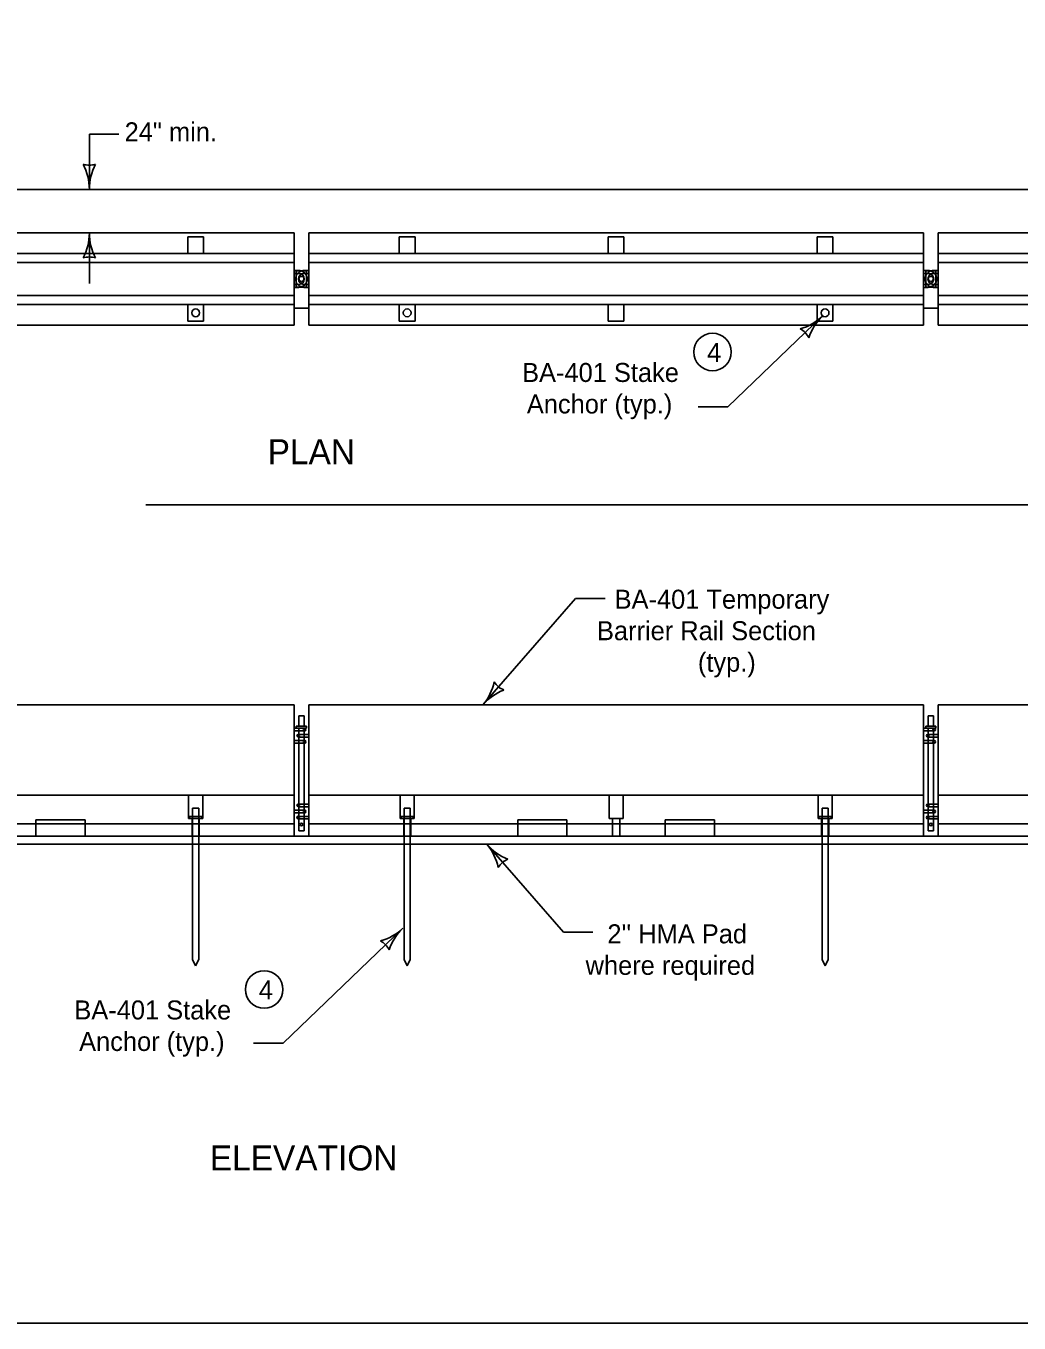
# Model space of a CAD drawing. Extents: x 10028 to 81668, y 3581 to 11018.
# Drawn here: x 22150 to 22944, y 7924 to 8962 of the extents above; entities that cross this region are included whole.
import ezdxf

# ---------------------------------------------------------------- set-up
doc = ezdxf.new("R2010")
doc.units = 0
for name, color, linetype in [('conPaving', 7, 'Continuous'), ('dsnCellsNorthArrow', 7, 'Continuous'), ('dsnTextTabulation', 7, 'Continuous'), ('Level 41', 7, 'Continuous'), ('Level 9', 7, 'Continuous'), ('SheetBorder', 7, 'Continuous')]:
    doc.layers.add(name, color=color, linetype=linetype)

msp = doc.modelspace()

# ---------------------------------------------------------------- linework, layer by layer
at = {"layer": 'conPaving'}
for p, q in [((22283.3, 8313.6), (22282.9, 8313.6)), ((22283.3, 8307.1), (22283.3, 8313.6)), ((22288.6, 8313.6), (22288.2, 8313.6)), ((22288.2, 8313.6), (22288.2, 8307.1)), ((22364.1, 8313.6), (22288.6, 8313.6)), ((22452.5, 8313.6), (22452.1, 8313.6)), ((22452.5, 8307.1), (22452.5, 8313.6)), ((22457.4, 8313.6), (22457.4, 8307.1)), ((22700.7, 8313.6), (22661.3, 8313.6)), ((22786.7, 8307.1), (22786.7, 8313.6)), ((22791.6, 8313.6), (22791.6, 8307.1)), ((22121.1, 8307.1), (22283.3, 8307.1)), ((22288.2, 8307.1), (22452.5, 8307.1)), ((22457.4, 8307.1), (22518.6, 8307.1)), ((22518.6, 8307.1), (22786.7, 8307.1)), ((22791.6, 8307.1), (22955.9, 8307.1))]:
    msp.add_line(p, q, dxfattribs=at)
for points in [[(22282.9, 8313.6), (22197.3, 8313.6), (22157.9, 8313.6), (22121.5, 8313.6), (22121.1, 8313.6)], [(22452.1, 8313.6), (22376.5, 8313.6), (22364.1, 8313.6)], [(22619.2, 8313.6), (22582.7, 8313.6), (22543.4, 8313.6), (22457.7, 8313.6), (22457.4, 8313.6)], [(22661.3, 8313.6), (22624.9, 8313.6), (22619.2, 8313.6)], [(22786.7, 8313.6), (22786.3, 8313.6), (22700.7, 8313.6)], [(22879.9, 8313.6), (22867.5, 8313.6), (22792, 8313.6), (22791.6, 8313.6)], [(22955.9, 8313.6), (22955.5, 8313.6), (22879.9, 8313.6)], [(22518.6, 8307.1), (22518.6, 8307.1)]]:
    msp.add_lwpolyline(points, dxfattribs=at)
msp.add_arc((22550.9, 8334.6), 42.5, 220.4336, 220.435, dxfattribs=at)
at = {"layer": 'dsnTextTabulation'}
for p, q in [((22200.7, 8831), (22200.7, 8875.1)), ((22200.7, 8875.1), (22224.3, 8875.1)), ((22364.4, 8796.1), (21872.9, 8796.1)), ((22200.7, 8755.8), (22200.7, 8796.1)), ((22364.4, 8722.4), (22364.4, 8796.1)), ((22867.8, 8796.1), (22376.3, 8796.1)), ((22376.3, 8722.4), (22376.3, 8796.1)), ((22867.8, 8722.4), (22867.8, 8796.1)), ((23371.2, 8796.1), (22879.7, 8796.1)), ((22879.7, 8722.4), (22879.7, 8796.1)), ((22364.4, 8779.8), (21872.9, 8779.8)), ((22867.8, 8779.8), (22376.3, 8779.8)), ((23371.2, 8779.8), (22879.7, 8779.8)), ((22364.4, 8772.4), (21872.9, 8772.4)), ((22867.8, 8772.4), (22376.3, 8772.4)), ((23371.2, 8772.4), (22879.7, 8772.4)), ((22364.4, 8746.2), (21872.9, 8746.2)), ((22364.4, 8738.8), (21872.9, 8738.8)), ((22867.8, 8746.2), (22376.3, 8746.2)), ((22867.8, 8738.8), (22376.3, 8738.8)), ((23371.2, 8746.2), (22879.7, 8746.2)), ((23371.2, 8738.8), (22879.7, 8738.8)), ((22711.4, 8657), (22787.1, 8729.7)), ((22364.4, 8722.4), (21872.9, 8722.4)), ((22867.8, 8722.4), (22376.3, 8722.4)), ((23371.2, 8722.4), (22879.7, 8722.4)), ((22687.7, 8657), (22711.4, 8657)), ((22245.9, 8578.7), (23377.1, 8578.7)), ((22515.3, 8418.5), (22589.6, 8503.7)), ((22589.6, 8503.7), (22613.2, 8503.7)), ((21872.9, 8418.5), (22364.4, 8418.5)), ((22364.4, 8313.9), (22364.4, 8418.5)), ((22376.3, 8313.9), (22376.3, 8418.5)), ((22376.3, 8418.5), (22867.8, 8418.5)), ((22867.8, 8313.9), (22867.8, 8418.5)), ((22879.7, 8313.9), (22879.7, 8418.5)), ((22879.7, 8418.5), (23371.2, 8418.5)), ((21872.9, 8346.4), (22364.4, 8346.4)), ((22376.3, 8346.4), (22867.8, 8346.4)), ((22879.7, 8346.4), (23371.2, 8346.4)), ((21872.9, 8323.4), (22364.4, 8323.4)), ((22157.9, 8326.7), (22197.3, 8326.7)), ((22157.9, 8313.6), (22157.9, 8323.4)), ((22197.3, 8313.6), (22197.3, 8323.4)), ((22376.3, 8323.4), (22867.8, 8323.4)), ((22543.4, 8326.7), (22582.7, 8326.7)), ((22543.4, 8313.6), (22543.4, 8323.4)), ((22582.7, 8313.6), (22582.7, 8323.4)), ((22661.3, 8326.7), (22700.7, 8326.7)), ((22661.3, 8313.6), (22661.3, 8323.4)), ((22700.7, 8313.6), (22700.7, 8323.4)), ((22879.7, 8323.4), (23371.2, 8323.4)), ((22079.3, 8313.6), (22157.9, 8313.6)), ((22197.3, 8313.6), (22364.1, 8313.6)), ((22376.5, 8313.6), (22543.4, 8313.6)), ((22582.7, 8313.6), (22661.3, 8313.6)), ((22700.7, 8313.6), (22867.5, 8313.6)), ((22879.9, 8313.6), (23046.8, 8313.6)), ((22518.6, 8307.1), (22579.8, 8236.8)), ((22355.6, 8148), (22451.5, 8239.9)), ((22579.8, 8236.8), (22603.4, 8236.8)), ((22332, 8148), (22355.6, 8148))]:
    msp.add_line(p, q, dxfattribs=at)
for centre in [(22699.1, 8700.9), (22340.5, 8190.9)]:
    msp.add_circle(centre, 15, dxfattribs=at)
for centre, radius, start, end in [((22200.7, 8866.7), 16.4, 252.2666, 287.7333), ((22158.2, 8831), 42.5, 360, 28.0725), ((22243.2, 8831), 42.5, 151.9275, 180), ((22158.2, 8796.1), 42.5, 331.9275, 360), ((22243.2, 8796.1), 42.5, 180, 208.0725), ((22200.7, 8760.5), 16.4, 72.2666, 107.7334), ((22757.7, 8760.3), 42.5, 285.7371, 313.8096), ((22816.5, 8699), 42.5, 133.8096, 161.8821), ((22761.4, 8705), 16.4, 26.0762, 61.5429), ((22483, 8446), 42.5, 319.5664, 347.6389), ((22538.5, 8445.6), 16.4, 211.833, 247.2997), ((22547.7, 8390.9), 42.5, 111.4939, 139.5664), ((22486.2, 8279.5), 42.5, 12.3611, 40.4336), ((22550.9, 8334.6), 42.5, 220.4336, 248.5061), ((22541.7, 8279.9), 16.4, 112.7003, 148.167), ((22422.1, 8270.6), 42.5, 285.7371, 313.8096), ((22480.9, 8209.3), 42.5, 133.8096, 161.8821), ((22425.8, 8215.3), 16.4, 26.0762, 61.5429)]:
    msp.add_arc(centre, radius, start, end, dxfattribs=at)
at = {"layer": 'Level 41'}
for p, q in [((22279.5, 8793), (22279.5, 8779.8)), ((22279.5, 8793), (22292, 8793)), ((22292, 8793), (22292, 8779.8)), ((22448.6, 8793), (22461.2, 8793)), ((22448.6, 8793), (22448.6, 8779.8)), ((22461.2, 8793), (22461.2, 8779.8)), ((22615.7, 8793), (22628.3, 8793)), ((22615.7, 8793), (22615.7, 8779.8)), ((22628.3, 8793), (22628.3, 8779.8)), ((22782.9, 8793), (22782.9, 8779.8)), ((22782.9, 8793), (22795.4, 8793)), ((22795.4, 8793), (22795.4, 8779.8)), ((22364.4, 8766), (22368.3, 8766)), ((22364.4, 8763.6), (22368.3, 8763.6)), ((22376.3, 8766), (22372.3, 8766)), ((22376.3, 8763.6), (22372.3, 8763.6)), ((22867.8, 8766), (22871.7, 8766)), ((22867.8, 8763.6), (22871.7, 8763.6)), ((22879.7, 8766), (22875.7, 8766)), ((22879.7, 8763.6), (22875.7, 8763.6)), ((22364.4, 8755), (22368.3, 8755)), ((22364.4, 8752.6), (22368.3, 8752.6)), ((22376.3, 8755), (22372.3, 8755)), ((22376.3, 8752.6), (22372.3, 8752.6)), ((22867.8, 8755), (22871.7, 8755)), ((22867.8, 8752.6), (22871.7, 8752.6)), ((22879.7, 8755), (22875.7, 8755)), ((22879.7, 8752.6), (22875.7, 8752.6)), ((22279.5, 8738.8), (22279.5, 8725.5)), ((22292, 8738.8), (22292, 8725.5)), ((22448.6, 8738.8), (22448.6, 8725.5)), ((22461.2, 8738.8), (22461.2, 8725.5)), ((22615.7, 8738.8), (22615.7, 8725.5)), ((22628.3, 8738.8), (22628.3, 8725.5)), ((22782.9, 8738.8), (22782.9, 8725.5)), ((22795.4, 8738.8), (22795.4, 8725.5)), ((22279.5, 8725.5), (22292, 8725.5)), ((22448.6, 8725.5), (22461.2, 8725.5)), ((22615.7, 8725.5), (22628.3, 8725.5)), ((22782.9, 8725.5), (22795.4, 8725.5)), ((22364.4, 8399.9), (22372.9, 8399.9)), ((22364.4, 8397.7), (22372.9, 8397.7)), ((22867.8, 8399.9), (22876.3, 8399.9)), ((22867.8, 8397.7), (22876.3, 8397.7)), ((22364.4, 8390), (22372.9, 8390)), ((22364.4, 8387.9), (22372.9, 8387.9)), ((22367.8, 8394.9), (22376.3, 8394.9)), ((22367.8, 8392.8), (22376.3, 8392.8)), ((22867.8, 8390), (22876.3, 8390)), ((22867.8, 8387.9), (22876.3, 8387.9)), ((22871.2, 8394.9), (22879.7, 8394.9)), ((22871.2, 8392.8), (22879.7, 8392.8)), ((22280.1, 8327.8), (22280.1, 8346.4)), ((22291.4, 8327.8), (22291.4, 8346.4)), ((22449.2, 8327.8), (22449.2, 8346.4)), ((22460.6, 8327.8), (22460.6, 8346.4)), ((22616.4, 8327.8), (22616.4, 8346.4)), ((22627.7, 8327.8), (22627.7, 8346.4)), ((22783.5, 8327.8), (22783.5, 8346.4)), ((22794.8, 8327.8), (22794.8, 8346.4)), ((22364.4, 8334.3), (22372.9, 8334.3)), ((22367.8, 8339.2), (22376.3, 8339.2)), ((22367.8, 8337.1), (22376.3, 8337.1)), ((22867.8, 8334.3), (22876.3, 8334.3)), ((22871.2, 8339.2), (22879.7, 8339.2)), ((22871.2, 8337.1), (22879.7, 8337.1)), ((22280.1, 8327.8), (22291.4, 8327.8)), ((22282.9, 8313.6), (22282.9, 8327.8)), ((22288.6, 8313.6), (22288.6, 8327.8)), ((22364.4, 8332.2), (22372.9, 8332.2)), ((22367.8, 8329.4), (22376.3, 8329.4)), ((22367.8, 8327.3), (22376.3, 8327.3)), ((22449.2, 8327.8), (22460.6, 8327.8)), ((22452.1, 8313.6), (22452.1, 8327.8)), ((22457.7, 8313.6), (22457.7, 8327.8)), ((22616.4, 8327.8), (22627.7, 8327.8)), ((22619.2, 8313.6), (22619.2, 8327.8)), ((22624.9, 8313.6), (22624.9, 8327.8)), ((22783.5, 8327.8), (22794.8, 8327.8)), ((22786.3, 8313.6), (22786.3, 8327.8)), ((22792, 8313.6), (22792, 8327.8)), ((22867.8, 8332.2), (22876.3, 8332.2)), ((22871.2, 8329.4), (22879.7, 8329.4)), ((22871.2, 8327.3), (22879.7, 8327.3))]:
    msp.add_line(p, q, dxfattribs=at)
for centre, radius in [((22285.7, 8732.2), 3.15), ((22454.9, 8732.2), 3.15), ((22789.1, 8732.2), 3.15), ((22372.9, 8398.8), 1.06), ((22876.3, 8398.8), 1.06), ((22367.8, 8393.9), 1.06), ((22372.9, 8389), 1.06), ((22871.2, 8393.9), 1.06), ((22876.3, 8389), 1.06), ((22367.8, 8338.2), 1.06), ((22372.9, 8333.3), 1.06), ((22871.2, 8338.2), 1.06), ((22876.3, 8333.3), 1.06), ((22367.8, 8328.4), 1.06), ((22871.2, 8328.4), 1.06)]:
    msp.add_circle(centre, radius, dxfattribs=at)
for centre, radius, start, end in [((22372.3, 8759.3), 6.68, 90, 270), ((22372.3, 8759.3), 4.33, 90, 270), ((22368.3, 8759.3), 6.68, 270, 90), ((22368.3, 8759.3), 4.33, 270, 90), ((22875.7, 8759.3), 6.68, 90, 270), ((22875.7, 8759.3), 4.33, 90, 270), ((22871.7, 8759.3), 6.68, 270, 90), ((22871.7, 8759.3), 4.33, 270, 90)]:
    msp.add_arc(centre, radius, start, end, dxfattribs=at)
at = {"layer": 'Level 9'}
for p, q in [((21357.6, 8831), (23377.1, 8831)), ((22376.3, 8796.1), (22867.8, 8796.1)), ((22879.7, 8796.1), (23371.2, 8796.1)), ((22364.4, 8766), (22368.3, 8766)), ((22366.2, 8765.8), (22374.4, 8765.8)), ((22366.2, 8752.7), (22366.2, 8765.8)), ((22369.8, 8765.8), (22370.9, 8765.8)), ((22372.3, 8766), (22376.3, 8766)), ((22374.4, 8765.8), (22374.4, 8752.7)), ((22867.8, 8766), (22871.7, 8766)), ((22869.6, 8765.8), (22877.8, 8765.8)), ((22869.6, 8752.7), (22869.6, 8765.8)), ((22873.2, 8765.8), (22874.3, 8765.8)), ((22875.7, 8766), (22879.7, 8766)), ((22877.8, 8765.8), (22877.8, 8752.7)), ((22368.3, 8752.6), (22364.4, 8752.6)), ((22374.4, 8752.7), (22366.2, 8752.7)), ((22371.1, 8752.7), (22369.5, 8752.7)), ((22376.3, 8752.6), (22372.3, 8752.6)), ((22871.7, 8752.6), (22867.8, 8752.6)), ((22877.8, 8752.7), (22869.6, 8752.7)), ((22874.5, 8752.7), (22872.9, 8752.7)), ((22879.7, 8752.6), (22875.7, 8752.6)), ((22364.4, 8736), (22376.3, 8736)), ((22364.4, 8736), (22376.3, 8736)), ((22867.8, 8736), (22879.7, 8736)), ((22867.8, 8736), (22879.7, 8736)), ((22368.3, 8409.7), (22372.4, 8409.7)), ((22368.3, 8401.5), (22368.3, 8409.7)), ((22372.4, 8409.7), (22372.4, 8401.5)), ((22871.7, 8409.7), (22875.8, 8409.7)), ((22871.7, 8401.5), (22871.7, 8409.7)), ((22875.8, 8409.7), (22875.8, 8401.5)), ((22366.2, 8401.5), (22374.4, 8401.5)), ((22366.2, 8399.9), (22366.2, 8401.5)), ((22374.4, 8399.9), (22366.2, 8399.9)), ((22368.3, 8317.9), (22368.3, 8399.9)), ((22372.4, 8399.9), (22372.4, 8317.9)), ((22374.4, 8401.5), (22374.4, 8399.9)), ((22869.6, 8401.5), (22877.8, 8401.5)), ((22869.6, 8399.9), (22869.6, 8401.5)), ((22877.8, 8399.9), (22869.6, 8399.9)), ((22871.7, 8317.9), (22871.7, 8399.9)), ((22875.8, 8399.9), (22875.8, 8317.9)), ((22877.8, 8401.5), (22877.8, 8399.9)), ((22288.2, 8336), (22283.3, 8336)), ((22283.3, 8336), (22283.3, 8329.4)), ((22288.2, 8336), (22283.3, 8336)), ((22283.3, 8214.8), (22283.3, 8336)), ((22288.2, 8329.4), (22288.2, 8336)), ((22288.2, 8214.8), (22288.2, 8336)), ((22457.4, 8336), (22452.5, 8336)), ((22452.5, 8336), (22452.5, 8329.4)), ((22457.4, 8336), (22452.5, 8336)), ((22452.5, 8214.8), (22452.5, 8336)), ((22457.4, 8329.4), (22457.4, 8336)), ((22457.4, 8214.8), (22457.4, 8336)), ((22791.6, 8336), (22786.7, 8336)), ((22786.7, 8336), (22786.7, 8329.4)), ((22791.6, 8336), (22786.7, 8336)), ((22786.7, 8214.8), (22786.7, 8336)), ((22791.6, 8329.4), (22791.6, 8336)), ((22791.6, 8214.8), (22791.6, 8336)), ((22157.9, 8323.4), (22157.9, 8326.7)), ((22157.9, 8323.4), (22197.3, 8323.4)), ((22197.3, 8323.4), (22197.3, 8326.7)), ((22280.8, 8329.4), (22280.8, 8327.8)), ((22283.3, 8329.4), (22280.8, 8329.4)), ((22280.8, 8327.8), (22280.8, 8329.4)), ((22280.8, 8327.8), (22282.9, 8327.8)), ((22282.9, 8327.8), (22283.3, 8327.8)), ((22288.2, 8329.4), (22283.3, 8329.4)), ((22283.3, 8329.4), (22283.3, 8327.8)), ((22283.3, 8327.8), (22283.3, 8329.4)), ((22283.3, 8329.4), (22288.2, 8329.4)), ((22288.2, 8327.8), (22283.3, 8327.8)), ((22283.3, 8327.8), (22283.3, 8323.4)), ((22283.3, 8327.8), (22288.2, 8327.8)), ((22288.2, 8323.4), (22283.3, 8323.4)), ((22283.3, 8323.4), (22283.3, 8313.6)), ((22283.3, 8323.4), (22288.2, 8323.4)), ((22288.2, 8327.8), (22288.2, 8329.4)), ((22288.2, 8329.4), (22288.2, 8327.8)), ((22288.2, 8323.4), (22288.2, 8327.8)), ((22288.2, 8313.6), (22288.2, 8323.4)), ((22450, 8329.4), (22450, 8327.8)), ((22452.5, 8329.4), (22450, 8329.4)), ((22450, 8327.8), (22450, 8329.4)), ((22450, 8327.8), (22452.1, 8327.8)), ((22452.1, 8327.8), (22452.5, 8327.8)), ((22457.4, 8329.4), (22452.5, 8329.4)), ((22452.5, 8329.4), (22452.5, 8327.8)), ((22452.5, 8327.8), (22452.5, 8329.4)), ((22452.5, 8329.4), (22457.4, 8329.4)), ((22457.4, 8327.8), (22452.5, 8327.8)), ((22452.5, 8327.8), (22452.5, 8323.4)), ((22452.5, 8327.8), (22457.4, 8327.8)), ((22457.4, 8323.4), (22452.5, 8323.4)), ((22452.5, 8323.4), (22452.5, 8313.6)), ((22452.5, 8323.4), (22457.4, 8323.4)), ((22457.4, 8327.8), (22457.4, 8329.4)), ((22457.4, 8329.4), (22457.4, 8327.8)), ((22457.4, 8323.4), (22457.4, 8327.8)), ((22457.4, 8313.6), (22457.4, 8323.4)), ((22543.4, 8323.4), (22543.4, 8326.7)), ((22543.4, 8323.4), (22582.7, 8323.4)), ((22582.7, 8323.4), (22582.7, 8326.7)), ((22661.3, 8323.4), (22661.3, 8326.7)), ((22661.3, 8323.4), (22700.7, 8323.4)), ((22700.7, 8323.4), (22700.7, 8326.7)), ((22784.2, 8329.4), (22784.2, 8327.8)), ((22786.7, 8329.4), (22784.2, 8329.4)), ((22784.2, 8327.8), (22784.2, 8329.4)), ((22784.2, 8327.8), (22786.3, 8327.8)), ((22786.3, 8327.8), (22786.7, 8327.8)), ((22791.6, 8329.4), (22786.7, 8329.4)), ((22786.7, 8329.4), (22786.7, 8327.8)), ((22786.7, 8327.8), (22786.7, 8329.4)), ((22786.7, 8329.4), (22791.6, 8329.4)), ((22791.6, 8327.8), (22786.7, 8327.8)), ((22786.7, 8327.8), (22786.7, 8323.4)), ((22786.7, 8327.8), (22791.6, 8327.8)), ((22791.6, 8323.4), (22786.7, 8323.4)), ((22786.7, 8323.4), (22786.7, 8313.6)), ((22786.7, 8323.4), (22791.6, 8323.4)), ((22791.6, 8327.8), (22791.6, 8329.4)), ((22791.6, 8329.4), (22791.6, 8327.8)), ((22791.6, 8323.4), (22791.6, 8327.8)), ((22791.6, 8313.6), (22791.6, 8323.4)), ((21034.4, 8313.6), (23909.2, 8313.6)), ((22288.2, 8313.6), (22283.3, 8313.6)), ((22283.3, 8313.6), (22283.3, 8307.1)), ((22283.3, 8313.6), (22288.2, 8313.6)), ((22288.2, 8307.1), (22288.2, 8313.6)), ((22364.1, 8313.6), (22364.4, 8313.9)), ((22372.4, 8317.9), (22368.3, 8317.9)), ((22376.3, 8313.9), (22376.5, 8313.6)), ((22457.4, 8313.6), (22452.5, 8313.6)), ((22452.5, 8313.6), (22452.5, 8307.1)), ((22452.5, 8313.6), (22457.4, 8313.6)), ((22457.4, 8307.1), (22457.4, 8313.6)), ((22791.6, 8313.6), (22786.7, 8313.6)), ((22786.7, 8313.6), (22786.7, 8307.1)), ((22786.7, 8313.6), (22791.6, 8313.6)), ((22791.6, 8307.1), (22791.6, 8313.6)), ((22867.5, 8313.6), (22867.8, 8313.9)), ((22875.8, 8317.9), (22871.7, 8317.9)), ((22879.7, 8313.9), (22879.9, 8313.6)), ((21357.6, 8307.1), (23377.1, 8307.1)), ((22288.2, 8307.1), (22283.3, 8307.1)), ((22283.3, 8307.1), (22283.3, 8214.8)), ((22283.3, 8307.1), (22288.2, 8307.1)), ((22288.2, 8214.8), (22288.2, 8307.1)), ((22457.4, 8307.1), (22452.5, 8307.1)), ((22452.5, 8307.1), (22452.5, 8214.8)), ((22452.5, 8307.1), (22457.4, 8307.1)), ((22457.4, 8214.8), (22457.4, 8307.1)), ((22791.6, 8307.1), (22786.7, 8307.1)), ((22786.7, 8307.1), (22786.7, 8214.8)), ((22786.7, 8307.1), (22791.6, 8307.1)), ((22791.6, 8214.8), (22791.6, 8307.1)), ((22283.3, 8214.8), (22285.7, 8209.8)), ((22283.3, 8214.8), (22285.7, 8209.8)), ((22285.7, 8209.8), (22288.2, 8214.8)), ((22285.7, 8209.8), (22288.2, 8214.8)), ((22452.5, 8214.8), (22454.9, 8209.8)), ((22452.5, 8214.8), (22454.9, 8209.8)), ((22454.9, 8209.8), (22457.4, 8214.8)), ((22454.9, 8209.8), (22457.4, 8214.8)), ((22786.7, 8214.8), (22789.1, 8209.8)), ((22786.7, 8214.8), (22789.1, 8209.8)), ((22789.1, 8209.8), (22791.6, 8214.8)), ((22789.1, 8209.8), (22791.6, 8214.8))]:
    msp.add_line(p, q, dxfattribs=at)
for points in [[(23377.1, 8831), (22043, 8831), (21858, 8831), (21858, 8831)], [(21872.9, 8796.1), (22043, 8796.1), (22364.4, 8796.1)], [(22364.4, 8796.1), (22364.4, 8779.8), (22364.4, 8772.4), (22364.4, 8766)], [(22376.3, 8766), (22376.3, 8772.4), (22376.3, 8779.8), (22376.3, 8796.1)], [(22867.8, 8796.1), (22867.8, 8779.8), (22867.8, 8772.4), (22867.8, 8766)], [(22879.7, 8766), (22879.7, 8772.4), (22879.7, 8779.8), (22879.7, 8796.1)], [(22364.4, 8752.6), (22364.4, 8746.2), (22364.4, 8738.8), (22364.4, 8736)], [(22376.3, 8736), (22376.3, 8738.8), (22376.3, 8746.2), (22376.3, 8752.6)], [(22867.8, 8752.6), (22867.8, 8746.2), (22867.8, 8738.8), (22867.8, 8736)], [(22879.7, 8736), (22879.7, 8738.8), (22879.7, 8746.2), (22879.7, 8752.6)], [(22280.8, 8329.4), (22290.7, 8329.4), (22290.7, 8327.8), (22280.8, 8327.8)], [(22290.7, 8327.8), (22290.7, 8329.4), (22288.2, 8329.4)], [(22288.2, 8327.8), (22288.6, 8327.8), (22290.7, 8327.8)], [(22450, 8329.4), (22459.8, 8329.4), (22459.8, 8327.8), (22450, 8327.8)], [(22459.8, 8327.8), (22459.8, 8329.4), (22457.4, 8329.4)], [(22457.4, 8327.8), (22457.7, 8327.8), (22459.8, 8327.8)], [(22784.2, 8329.4), (22794.1, 8329.4), (22794.1, 8327.8), (22784.2, 8327.8)], [(22794.1, 8327.8), (22794.1, 8329.4), (22791.6, 8329.4)], [(22791.6, 8327.8), (22792, 8327.8), (22794.1, 8327.8)]]:
    msp.add_lwpolyline(points, dxfattribs=at)
for centre, radius in [((22370.3, 8759.3), 2.05), ((22873.7, 8759.3), 2.05), ((22370.3, 8322.9), 1.02), ((22873.7, 8322.9), 1.02)]:
    msp.add_circle(centre, radius, dxfattribs=at)
for centre, start, end in [((22368.3, 8759.3), 77.6043, 90), ((22372.3, 8759.3), 90, 102.3957), ((22871.7, 8759.3), 77.6043, 90), ((22875.7, 8759.3), 90, 102.3957), ((22368.3, 8759.3), 270, 280.2309), ((22372.3, 8759.3), 259.7691, 270), ((22871.7, 8759.3), 270, 280.2309), ((22875.7, 8759.3), 259.7691, 270)]:
    msp.add_arc(centre, 6.68, start, end, dxfattribs=at)
at = {"layer": 'SheetBorder'}
msp.add_lwpolyline([(20932.5, 9944), (24067.5, 9944), (24067.5, 7924), (20932.5, 7924)], close=True, dxfattribs=at)

# ---------------------------------------------------------------- texts
at = {"layer": 'dsnCellsNorthArrow'}
for s, height, p in [('24" min.', 15.2, (22228.9, 8869.4)), ('BA-401 Stake', 15.2, (22546.8, 8676.9)), ('Anchor (typ.)', 15.2, (22550.6, 8651.7)), ('PLAN', 20, (22343.3, 8611.1)), ('BA-401 Temporary', 15.2, (22620.8, 8495.5)), ('Barrier Rail Section', 15.2, (22606.7, 8470.3)), ('(typ.)', 15.2, (22687.4, 8445.1)), ("2'' HMA Pad", 15.2, (22615, 8227.8)), ('where required', 15.2, (22597.6, 8202.6)), ('BA-401 Stake', 15.2, (22188.7, 8166.9)), ('Anchor (typ.)', 15.2, (22192.5, 8141.7)), ('ELEVATION', 20, (22297, 8046.1))]:
    msp.add_text(s, height=height, dxfattribs=at).set_placement(p)
at = {"layer": 'dsnTextTabulation'}
for p in [(22694.8, 8693), (22336.2, 8182.9)]:
    msp.add_text('4', height=15.2, dxfattribs=at).set_placement(p)

doc.saveas('drawing.dxf')
